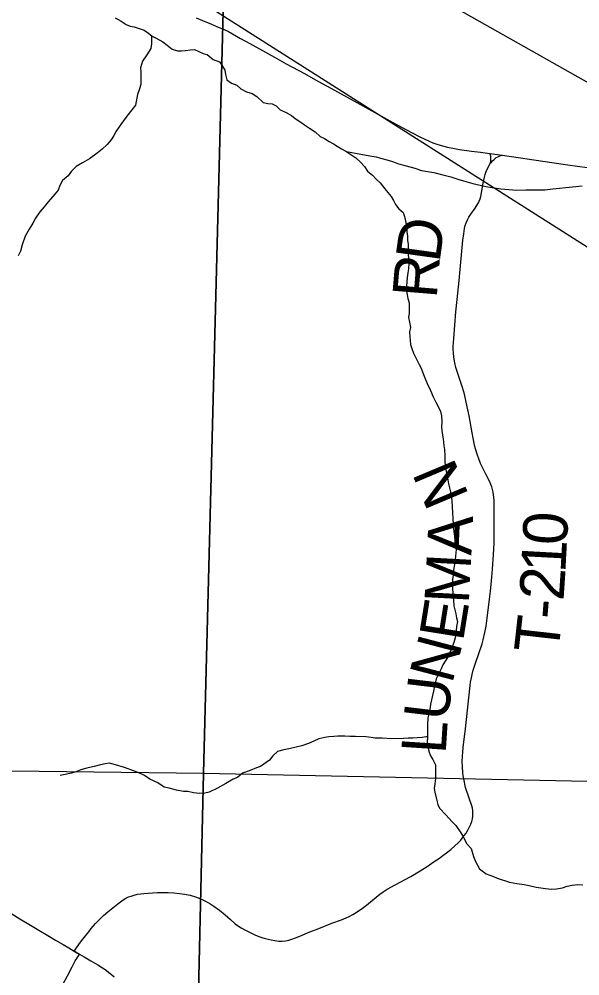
# Model space of a CAD drawing. Extents: x 0 to 34, y 0 to 22.
# Drawn here: x 7.311 to 8.027, y 14.622 to 15.844 of the extents above; entities that cross this region are included whole.
import ezdxf

# ---------------------------------------------------------------- set-up
doc = ezdxf.new("R2010")
doc.units = 0
for name, color, linetype in [('GM_X_Corporation', 7, 'Continuous'), ('GM_X_Interstate_Route', 7, 'Continuous'), ('GM_X_Minor_Lake', 7, 'Continuous'), ('GM_X_Section', 7, 'Continuous'), ('GM_X_Township_Road_Text', 7, 'Continuous'), ('GM_X_Unincorporated_Text', 7, 'Continuous'), ('SH_Data', 7, 'Continuous')]:
    doc.layers.add(name, color=color, linetype=linetype)

msp = doc.modelspace()

# ---------------------------------------------------------------- linework, layer by layer
at = {"layer": 'GM_X_Corporation'}
for points in [[(7.5371, 15.8459), (7.5453, 15.8422), (7.5565, 15.8377), (7.5644, 15.8343), (7.5738, 15.8303), (7.5783, 15.8281), (7.5939, 15.8195), (7.6055, 15.813), (7.6217, 15.804), (7.637, 15.7955), (7.6523, 15.7871), (7.6754, 15.7745), (7.6925, 15.765), (7.7092, 15.7557), (7.7263, 15.7464), (7.7425, 15.7376), (7.7882, 15.7122), (7.8121, 15.6991), (7.8239, 15.6931), (7.8339, 15.6885), (7.8397, 15.6862), (7.8457, 15.684), (7.8534, 15.6817), (7.8583, 15.6805), (7.8672, 15.6787), (7.8734, 15.6774), (7.8889, 15.6754), (7.9004, 15.6741), (7.9123, 15.6725), (7.9283, 15.6702), (7.9917, 15.6609), (8.0118, 15.658), (8.0367, 15.6547)], [(7.3001, 14.7018), (7.3119, 14.6945), (7.3256, 14.6863), (7.336, 14.6801), (7.3476, 14.6732), (7.3574, 14.6673), (7.367, 14.6616), (7.3743, 14.6573), (7.381, 14.6533)], [(7.381, 14.6533), (7.3848, 14.6511), (7.3881, 14.6492)], [(7.3881, 14.6492), (7.3941, 14.6457), (7.4026, 14.6409), (7.4116, 14.6355), (7.4175, 14.6318), (7.4219, 14.6288), (7.4257, 14.626), (7.4291, 14.6234), (7.4325, 14.6202)]]:
    msp.add_lwpolyline(points, dxfattribs=at)
at = {"layer": 'GM_X_Interstate_Route'}
for points in [[(7.8804, 14.9306), (7.8808, 14.9336), (7.8872, 14.9926), (7.8878, 14.9967), (7.8887, 15.0022), (7.8898, 15.0068), (7.8912, 15.0123), (7.8947, 15.0238), (7.8973, 15.0311), (7.9024, 15.046), (7.9039, 15.0509), (7.906, 15.0603), (7.9077, 15.0684), (7.909, 15.0788), (7.912, 15.1029), (7.9131, 15.113), (7.915, 15.1309), (7.9157, 15.1414), (7.917, 15.1601), (7.9177, 15.1743), (7.9178, 15.1795), (7.918, 15.2253), (7.9179, 15.2289), (7.9172, 15.2365), (7.9167, 15.2395), (7.9158, 15.2431), (7.9148, 15.2465), (7.9137, 15.2496), (7.9124, 15.2527), (7.9074, 15.2625), (7.9021, 15.2728), (7.9006, 15.2762), (7.8977, 15.2835), (7.8964, 15.287), (7.8939, 15.2952), (7.8928, 15.2997), (7.8909, 15.3086), (7.8897, 15.3156), (7.8861, 15.3372), (7.8833, 15.3489), (7.8798, 15.365), (7.8773, 15.3736), (7.8689, 15.399), (7.8676, 15.4049), (7.8663, 15.4122), (7.8658, 15.4178), (7.8654, 15.4219), (7.8656, 15.4258), (7.8662, 15.4358), (7.869, 15.47), (7.8705, 15.4857), (7.8732, 15.5101), (7.878, 15.5615), (7.879, 15.5696), (7.8801, 15.5764), (7.881, 15.5805), (7.8821, 15.5839), (7.8837, 15.5875), (7.8855, 15.5909), (7.888, 15.595), (7.8934, 15.6025), (7.8963, 15.6069), (7.8977, 15.6092), (7.8988, 15.6113), (7.9, 15.6145), (7.9007, 15.6174), (7.9021, 15.6246), (7.9038, 15.6343), (7.9052, 15.6406), (7.9065, 15.6456), (7.9077, 15.6492), (7.9129, 15.6601), (7.9143, 15.6614), (7.9157, 15.6629), (7.9173, 15.6645), (7.9186, 15.6658), (7.9205, 15.6672), (7.9226, 15.6683), (7.9241, 15.669), (7.9262, 15.6697), (7.9283, 15.6702)], [(7.9129, 15.6601), (7.9132, 15.6608), (7.9136, 15.6621), (7.9138, 15.6637), (7.9135, 15.669), (7.9132, 15.6703), (7.9127, 15.6715), (7.9123, 15.6725)], [(7.381, 14.6533), (7.3895, 14.6647), (7.3924, 14.6686), (7.3957, 14.6729), (7.3998, 14.678), (7.4029, 14.6819), (7.4086, 14.6884), (7.4128, 14.6927), (7.4189, 14.6986), (7.4243, 14.7033), (7.4287, 14.7069), (7.437, 14.7136), (7.4437, 14.7187), (7.4474, 14.7208), (7.4507, 14.7224), (7.454, 14.7236), (7.4579, 14.7248), (7.4621, 14.7258), (7.4662, 14.7264), (7.4703, 14.7269), (7.4813, 14.7278), (7.4875, 14.728), (7.4943, 14.7282), (7.5012, 14.728), (7.5087, 14.7276), (7.516, 14.727), (7.5224, 14.726), (7.5293, 14.7245), (7.5364, 14.7224), (7.5416, 14.7203), (7.5455, 14.7186), (7.549, 14.7169), (7.552, 14.7154), (7.5557, 14.7133), (7.5595, 14.7108), (7.5667, 14.7055), (7.5742, 14.6994), (7.5808, 14.6935), (7.5871, 14.6881), (7.5911, 14.6851), (7.5946, 14.6829), (7.6003, 14.6799), (7.6071, 14.6764), (7.6121, 14.6741), (7.617, 14.672), (7.6211, 14.6705), (7.6251, 14.6693), (7.6292, 14.6684), (7.6329, 14.6677), (7.6376, 14.6669), (7.6428, 14.6661), (7.647, 14.6659), (7.6512, 14.6663), (7.6553, 14.6671), (7.6593, 14.6683), (7.664, 14.6701), (7.6694, 14.6722), (7.6825, 14.6777), (7.6937, 14.6821), (7.7105, 14.6888), (7.723, 14.6933), (7.7289, 14.6956), (7.7328, 14.6973), (7.7372, 14.6998), (7.7417, 14.7026), (7.7498, 14.7082), (7.7546, 14.712), (7.7597, 14.7162), (7.7717, 14.7258), (7.776, 14.7289), (7.7813, 14.7324), (7.7915, 14.738), (7.8113, 14.7486), (7.8231, 14.7556), (7.8322, 14.7613), (7.8413, 14.7676), (7.8478, 14.772), (7.8524, 14.7752), (7.8571, 14.7789), (7.8624, 14.7831), (7.8676, 14.7877), (7.8718, 14.7916), (7.8751, 14.7951), (7.8792, 14.8003), (7.882, 14.8038), (7.8844, 14.8078), (7.8865, 14.8119), (7.8881, 14.8153), (7.8892, 14.8187), (7.89, 14.8221), (7.8906, 14.8254), (7.8904, 14.833), (7.89, 14.8357), (7.8893, 14.8387), (7.8821, 14.8596), (7.8814, 14.8622), (7.879, 14.8734), (7.8784, 14.877), (7.8778, 14.8814), (7.8772, 14.8886), (7.8771, 14.8954), (7.8774, 14.9024), (7.8777, 14.9075), (7.8782, 14.9136), (7.8804, 14.9306)], [(7.3671, 14.6115), (7.3728, 14.6217), (7.3786, 14.6332), (7.3827, 14.6407), (7.3846, 14.6438), (7.3881, 14.6492)], [(7.3881, 14.6492), (7.3848, 14.6511), (7.381, 14.6533)]]:
    msp.add_lwpolyline(points, dxfattribs=at)
at = {"layer": 'GM_X_Minor_Lake'}
for points in [[(7.5725, 15.8874), (7.5466, 14.8803), (6.5307, 14.8925), (6.553, 15.9139)], [(7.5725, 15.8874), (8.5869, 15.8686), (8.5685, 14.859), (7.5466, 14.8803)]]:
    msp.add_lwpolyline(points, close=True, dxfattribs=at)
at = {"layer": 'GM_X_Township_Road_Text'}
for points in [[(7.4336, 15.8456), (7.4413, 15.8415), (7.4478, 15.8374), (7.4527, 15.8352), (7.4577, 15.8342), (7.4641, 15.8323), (7.4706, 15.8302), (7.476, 15.8261), (7.4809, 15.8223), (7.4859, 15.8197), (7.4943, 15.8149), (7.5, 15.8108), (7.5065, 15.8056), (7.5134, 15.8034), (7.5183, 15.8035)], [(7.4799, 15.8231), (7.4799, 15.8124), (7.4793, 15.8067), (7.4741, 15.7986), (7.4685, 15.7905), (7.466, 15.7818), (7.4664, 15.7768), (7.4666, 15.7658), (7.4663, 15.7604), (7.4649, 15.7551), (7.4623, 15.7478), (7.4606, 15.739), (7.4595, 15.7341), (7.455, 15.7283), (7.4502, 15.7221), (7.4446, 15.7152), (7.4387, 15.7064), (7.435, 15.701), (7.432, 15.6956), (7.4287, 15.6898), (7.4235, 15.684), (7.4172, 15.6779), (7.4108, 15.6728), (7.4007, 15.6658), (7.392, 15.6603), (7.3838, 15.656), (7.3778, 15.6499), (7.3737, 15.6437), (7.3662, 15.6379), (7.3629, 15.6314), (7.3607, 15.6256), (7.3566, 15.6206), (7.3481, 15.6106), (7.3429, 15.6044), (7.3373, 15.5979), (7.3317, 15.5898), (7.3284, 15.5836), (7.3236, 15.5756), (7.3188, 15.5667), (7.3148, 15.5556), (7.3127, 15.5476), (7.3097, 15.5415)], [(7.5183, 15.8035), (7.5236, 15.804), (7.53, 15.8048), (7.5349, 15.8053), (7.546, 15.8001), (7.5513, 15.799), (7.559, 15.7927), (7.567, 15.7894), (7.5708, 15.7841), (7.5736, 15.7788), (7.5744, 15.7735), (7.5764, 15.7667), (7.5821, 15.7622), (7.589, 15.7597), (7.594, 15.7552), (7.6012, 15.7511), (7.6088, 15.7489), (7.6146, 15.7452), (7.6226, 15.7377), (7.6287, 15.7363), (7.634, 15.736), (7.6394, 15.7334), (7.6444, 15.7282), (7.652, 15.7248), (7.6588, 15.7211), (7.6638, 15.717), (7.6707, 15.7126), (7.6757, 15.7092), (7.6818, 15.7048), (7.6891, 15.6999), (7.6956, 15.6943), (7.7009, 15.6917), (7.707, 15.6876), (7.7124, 15.6847), (7.7173, 15.6817), (7.7227, 15.6784), (7.7284, 15.6754), (7.7361, 15.6702), (7.741, 15.6668), (7.7472, 15.6612), (7.7522, 15.656), (7.756, 15.6499), (7.7626, 15.6447), (7.7672, 15.6398), (7.7722, 15.635), (7.778, 15.6274), (7.7822, 15.6226), (7.7861, 15.6173), (7.7892, 15.6124), (7.7919, 15.6071), (7.7961, 15.6015), (7.8015, 15.597), (7.8035, 15.592), (7.8051, 15.5841), (7.8059, 15.5788), (7.8064, 15.5723), (7.8072, 15.5666), (7.8073, 15.5617), (7.8078, 15.5563), (7.8079, 15.5442), (7.8084, 15.5377), (7.8089, 15.532), (7.8086, 15.5251), (7.8075, 15.5198), (7.8065, 15.5141), (7.8062, 15.5084), (7.8056, 15.4977), (7.8068, 15.4924), (7.8076, 15.4871), (7.8092, 15.4818), (7.8093, 15.4761), (7.8091, 15.4684), (7.8084, 15.4627), (7.8096, 15.457), (7.8108, 15.4502), (7.8098, 15.4445), (7.8102, 15.4384), (7.8111, 15.4285), (7.8127, 15.4232), (7.8147, 15.4171), (7.8221, 15.4028), (7.8245, 15.3979), (7.8268, 15.3922), (7.8292, 15.3858), (7.8323, 15.3786), (7.8366, 15.3695), (7.8401, 15.3616), (7.8433, 15.3548), (7.8464, 15.3491), (7.8491, 15.3427), (7.8507, 15.337), (7.8508, 15.3298), (7.8506, 15.3229), (7.8514, 15.3149), (7.8527, 15.3077), (7.8535, 15.2994), (7.8544, 15.2941), (7.8549, 15.2864), (7.855, 15.2788), (7.8554, 15.2731), (7.8571, 15.264)], [(7.7292, 15.6749), (7.7474, 15.6715), (7.7592, 15.6694), (7.7671, 15.668), (7.7728, 15.6666), (7.7823, 15.664), (7.7892, 15.6619), (7.7957, 15.6593), (7.8055, 15.6568), (7.8166, 15.6535), (7.825, 15.6506), (7.8409, 15.6482), (7.8523, 15.6453), (7.8626, 15.6424), (7.8713, 15.6395), (7.8785, 15.6373), (7.8907, 15.6341), (7.9074, 15.6302), (7.9264, 15.6274), (7.9469, 15.6255), (7.9582, 15.626), (7.9707, 15.6258), (7.9824, 15.626), (7.993, 15.6273), (8.018, 15.63), (8.0301, 15.6309)], [(7.8571, 15.264), (7.8583, 15.258), (7.8596, 15.2504), (7.862, 15.2401), (7.8637, 15.2291), (7.8642, 15.2207), (7.8646, 15.2131), (7.8651, 15.2063), (7.8656, 15.1976), (7.8665, 15.1892), (7.867, 15.1835), (7.8678, 15.1774), (7.869, 15.1721), (7.8691, 15.1664), (7.8685, 15.158), (7.8675, 15.1504), (7.8661, 15.1397), (7.8654, 15.1332), (7.8648, 15.1283), (7.8646, 15.1157), (7.8654, 15.107), (7.8659, 15.1016), (7.8664, 15.0944), (7.8676, 15.0891), (7.8688, 15.0842), (7.8696, 15.0792), (7.8708, 15.0743), (7.8698, 15.0682), (7.8691, 15.0625), (7.8681, 15.0537), (7.8663, 15.0476), (7.863, 15.0384), (7.859, 15.0296), (7.8523, 15.0188), (7.8501, 15.0139), (7.8439, 15.0012), (7.8417, 14.992), (7.8403, 14.9855), (7.8364, 14.9687), (7.8358, 14.9615), (7.8329, 14.9512), (7.8326, 14.9424), (7.8325, 14.9272), (7.8322, 14.9196), (7.833, 14.9146), (7.8343, 14.9086), (7.8366, 14.9029), (7.8397, 14.898), (7.8428, 14.8912), (7.8431, 14.8737), (7.8421, 14.8668), (7.8414, 14.8611), (7.8422, 14.8562), (7.8442, 14.8475), (7.8459, 14.8406), (7.8482, 14.8357), (7.8563, 14.8275), (7.8644, 14.8185), (7.869, 14.8136), (7.8744, 14.8057), (7.8775, 14.8008), (7.8829, 14.7902), (7.8883, 14.7842), (7.8915, 14.774), (7.8939, 14.7675), (7.8993, 14.7585), (7.9077, 14.7521), (7.9169, 14.7485), (7.9218, 14.7463), (7.9374, 14.7415), (7.9469, 14.7398), (7.956, 14.7384), (7.9625, 14.737), (7.9716, 14.7348), (7.9833, 14.7331), (7.9913, 14.7325), (7.9977, 14.7326), (8.0053, 14.7342), (8.0113, 14.7362), (8.0174, 14.7374), (8.0245, 14.7383), (8.031, 14.738)], [(7.8323, 14.9272), (7.831, 14.9268), (7.8257, 14.9263), (7.8196, 14.9259), (7.8139, 14.9254), (7.8079, 14.9253), (7.8022, 14.9248), (7.7871, 14.9246), (7.7746, 14.9252), (7.7659, 14.9254), (7.7605, 14.9261), (7.7537, 14.9268), (7.7408, 14.9273), (7.7333, 14.9276), (7.7272, 14.9279), (7.7181, 14.9277), (7.7132, 14.9273), (7.7064, 14.9272), (7.7015, 14.926), (7.6939, 14.9243), (7.6875, 14.9215), (7.6808, 14.9184), (7.6721, 14.9156), (7.6578, 14.912), (7.6491, 14.9103), (7.6412, 14.9083), (7.6352, 14.9029), (7.6307, 14.8971), (7.6191, 14.8893), (7.6142, 14.8873), (7.6059, 14.8841), (7.5965, 14.8806), (7.5898, 14.8751), (7.5845, 14.8728), (7.5751, 14.8673), (7.5642, 14.8614), (7.5537, 14.8563), (7.548, 14.8551), (7.5412, 14.8546), (7.5336, 14.8556), (7.5264, 14.857), (7.5211, 14.8573), (7.512, 14.8587), (7.5025, 14.8612), (7.4961, 14.8627), (7.488, 14.8683), (7.4777, 14.873), (7.4709, 14.8775), (7.4628, 14.8816), (7.4571, 14.8834), (7.4457, 14.8878), (7.4339, 14.8914), (7.4263, 14.8932), (7.4207, 14.8923), (7.415, 14.8911), (7.4067, 14.8891), (7.3973, 14.887), (7.3897, 14.885), (7.3833, 14.8823), (7.378, 14.8807), (7.3697, 14.879), (7.3633, 14.8778)]]:
    msp.add_lwpolyline(points, dxfattribs=at)
at = {"layer": 'GM_X_Unincorporated_Text'}
for points in [[(6.5122, 14.1), (7.5285, 14.1), (7.5466, 14.8803), (6.5307, 14.8925)], [(7.5285, 14.1), (8.5434, 14.1), (8.5685, 14.859), (7.5466, 14.8803)]]:
    msp.add_lwpolyline(points, close=True, dxfattribs=at)
at = {"layer": 'SH_Data'}
msp.add_lwpolyline([(9.2998, 15.0505), (5.0551, 17.4465), (9.2998, 14.751)], close=True, dxfattribs=at)

# ---------------------------------------------------------------- texts
at = {"layer": 'GM_X_Section'}
for s, rotation, p in [('D', 82.1543, (7.848, 15.5319)), ('R', 85.2642, (7.8443, 15.4862)), ('N', 112.8266, (7.8861, 15.2352)), ('A', 87.4723, (7.8887, 15.1584)), ('0', 87.0769, (8.0106, 15.171)), ('1', 86.9061, (8.0087, 15.1358)), ('M', 86.9713, (7.8854, 15.0963)), ('2', 86.1942, (8.0064, 15.1001)), ('E', 80.8826, (7.878, 15.0478)), ('-', 85.4214, (8.0044, 15.0761)), ('T', 83.558, (7.9995, 15.0318)), ('N', 75.2711, (7.864, 14.9935)), ('U', 83.227, (7.8585, 14.9459)), ('L', 86.2817, (7.8558, 14.9043))]:
    msp.add_text(s, height=0.0568, rotation=rotation, dxfattribs=at).set_placement(p)

doc.saveas('drawing.dxf')
